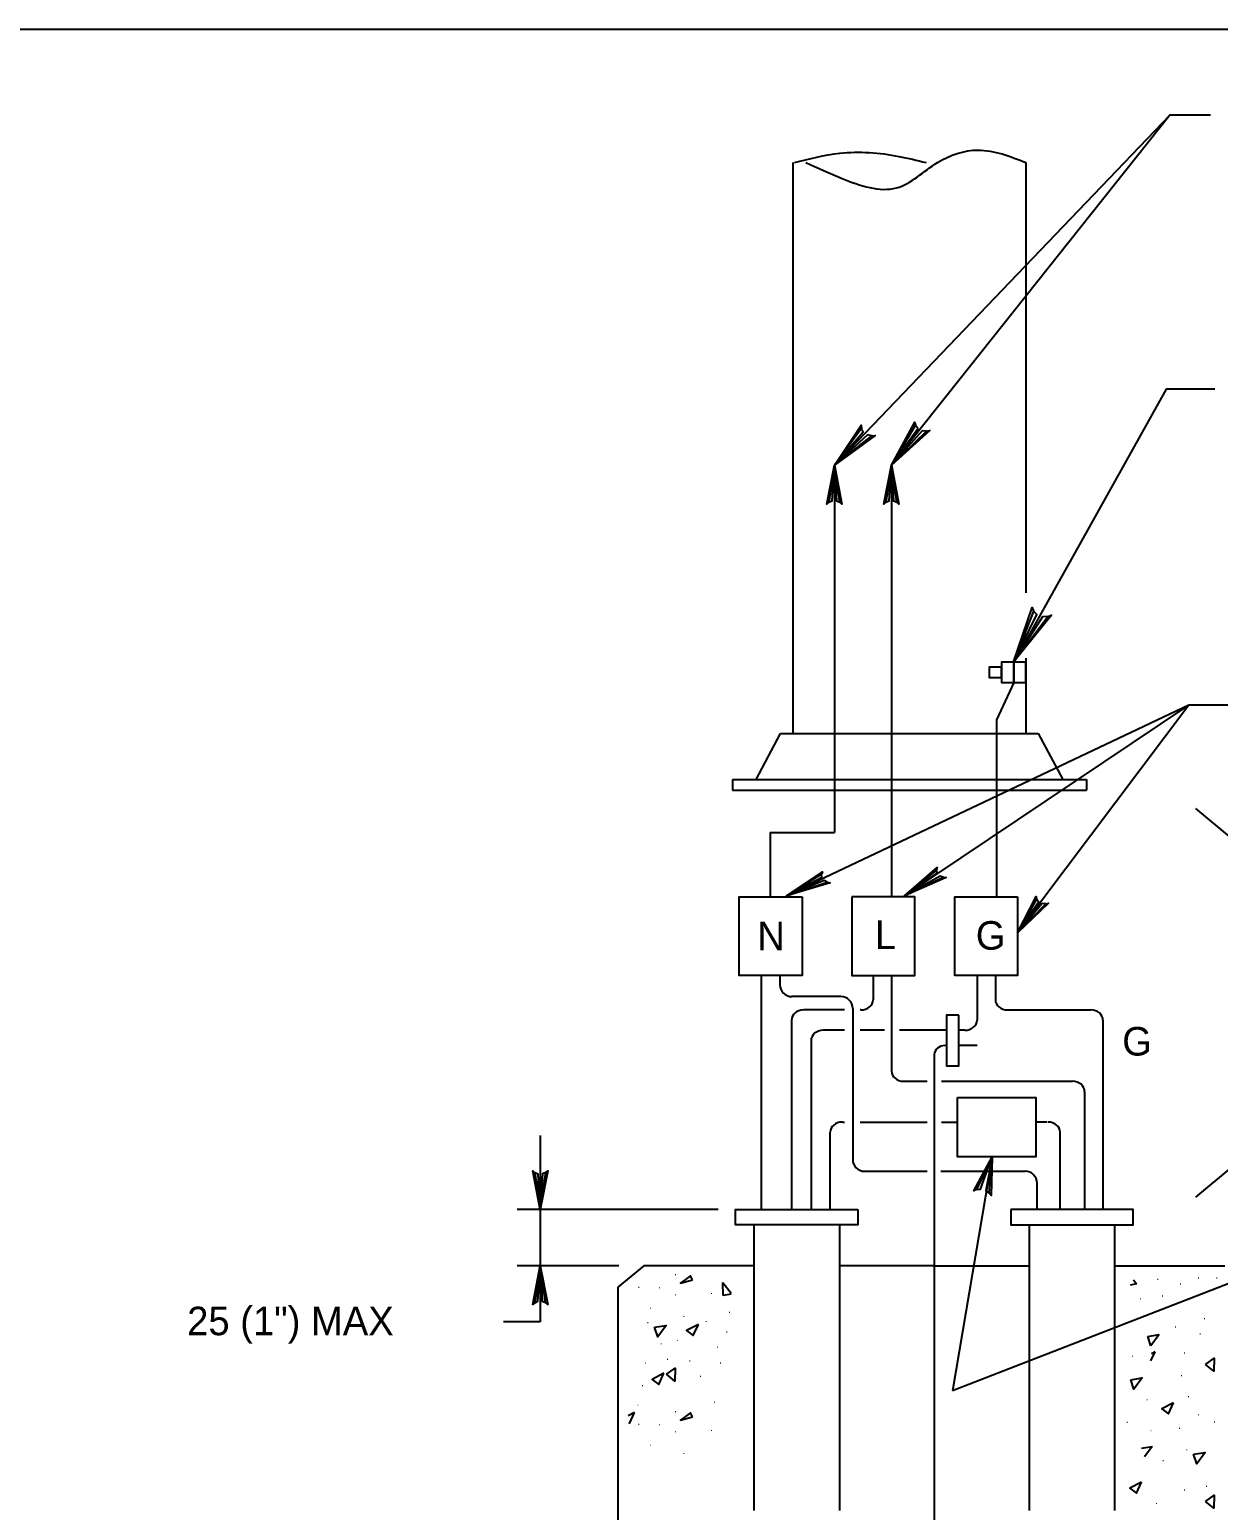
# Model space of a CAD drawing. Extents: x 638448 to 639352, y 297825 to 299013.
# Drawn here: x 639008.9 to 639148.9, y 298230 to 298404.3 of the extents above; entities that cross this region are included whole.
import ezdxf

# ---------------------------------------------------------------- set-up
doc = ezdxf.new("R2010")
doc.units = 0
for name, color, linetype in [('1', 7, 'Continuous'), ('2', 7, 'Continuous'), ('3', 7, 'Continuous')]:
    doc.layers.add(name, color=color, linetype=linetype)

msp = doc.modelspace()

# ---------------------------------------------------------------- linework, layer by layer
at = {"layer": '1'}
for p, q in [((639145.42, 298324.79), (639098.03, 298302.32)), ((639091.67, 298316.03), (639091.67, 298314.77)), ((639133.34, 298316.03), (639133.34, 298314.77)), ((639122.26, 298271.59), (639117.57, 298244.07)), ((639157.76, 298259.65), (639117.57, 298244.07))]:
    msp.add_line(p, q, dxfattribs=at)
msp.add_lwpolyline([(639272.65, 297840.29), (639272.65, 298404.29), (638486.65, 298404.29), (638486.65, 297840.29), (639272.65, 297840.29), (639272.65, 297866.65), (639072.65, 297866.65), (639072.65, 297931.33), (639272.65, 297931.33), (639272.65, 297960.29), (639072.65, 297960.29), (639072.65, 297840.29), (639151.45, 297840.29), (639151.45, 297866.65), (639151.45, 297840.29), (639228.45, 297840.29), (639228.45, 297866.65), (639228.45, 297854.33), (639272.65, 297854.33)], dxfattribs=at)
for centre, start, end in [((639098.66, 298291.87), 180, 270), ((639104.43, 298289.07), 0, 90), ((639107.23, 298271.31), 180, 270), ((639126.13, 298268.51), 0, 90)]:
    msp.add_arc(centre, 1.4, start, end, dxfattribs=at)
at = {"layer": '2'}
for p, q in [((639098.78, 298388.63), (639098.78, 298321.43)), ((639126.23, 298388.63), (639126.23, 298337.99)), ((639103.69, 298353.01), (639103.69, 298309.78)), ((639110.39, 298353.01), (639110.39, 298302.21)), ((639126.23, 298330.3), (639126.23, 298321.43)), ((639124.79, 298327.43), (639122.75, 298323.03)), ((639122.75, 298323.03), (639122.75, 298302.21)), ((639094.46, 298316.03), (639097.34, 298321.43)), ((639097.34, 298321.43), (639127.67, 298321.43)), ((639127.67, 298321.43), (639130.55, 298316.03)), ((639091.67, 298316.03), (639133.34, 298316.03)), ((639091.67, 298314.77), (639133.34, 298314.77)), ((639096.11, 298309.78), (639103.69, 298309.78)), ((639096.11, 298309.78), (639096.11, 298302.21)), ((639095.04, 298292.99), (639095.04, 298265.39)), ((639097.26, 298292.85), (639097.26, 298291.87)), ((639108.23, 298292.99), (639108.23, 298290.1)), ((639110.39, 298292.99), (639110.39, 298281.7)), ((639120.47, 298292.99), (639120.47, 298287.7)), ((639122.63, 298292.99), (639122.63, 298290.1)), ((639104.43, 298290.47), (639098.66, 298290.47)), ((639098.62, 298287.7), (639098.62, 298265.39)), ((639104.85, 298288.9), (639100.06, 298288.9)), ((639105.83, 298289.07), (639105.83, 298271.31)), ((639106.79, 298288.9), (639106.71, 298288.9)), ((639124.07, 298288.9), (639133.85, 298288.9)), ((639135.29, 298287.7), (639135.29, 298265.39)), ((639104.85, 298286.5), (639102.37, 298286.5)), ((639109.56, 298286.5), (639106.71, 298286.5)), ((639116.87, 298286.5), (639111.34, 298286.5)), ((639119.03, 298286.5), (639118.31, 298286.5)), ((639100.93, 298285.3), (639100.93, 298265.39)), ((639116.87, 298284.7), (639116.72, 298284.7)), ((639120.47, 298284.7), (639118.31, 298284.7)), ((639115.43, 298283.62), (639115.43, 298193.63)), ((639111.83, 298280.5), (639114.61, 298280.5)), ((639116.29, 298280.5), (639131.69, 298280.5)), ((639133.13, 298279.3), (639133.13, 298265.39)), ((639104.61, 298275.7), (639104.85, 298275.7)), ((639106.71, 298275.7), (639114.61, 298275.7)), ((639116.29, 298275.7), (639118.17, 298275.7)), ((639128.67, 298275.7), (639127.4, 298275.7)), ((639069.04, 298274.1), (639069.04, 298265.39)), ((639103.17, 298265.39), (639103.17, 298274.5)), ((639130.25, 298265.39), (639130.25, 298274.5)), ((639107.23, 298269.91), (639114.58, 298269.91)), ((639116.22, 298269.91), (639126.13, 298269.91)), ((639127.53, 298265.39), (639127.53, 298268.51)), ((639090.01, 298265.39), (639066.33, 298265.39)), ((639069.04, 298265.39), (639069.04, 298258.79)), ((639094.19, 298263.59), (639094.19, 298229.99)), ((639104.27, 298263.59), (639104.27, 298229.99)), ((639126.59, 298263.59), (639126.59, 298229.99)), ((639136.67, 298263.59), (639136.67, 298229.99)), ((639078.3, 298258.79), (639066.33, 298258.79)), ((639081.23, 298258.79), (639078.17, 298256.25)), ((639094.19, 298258.79), (639081.23, 298258.79)), ((639115.43, 298258.79), (639104.27, 298258.79)), ((639115.43, 298258.79), (639126.59, 298258.79)), ((639136.67, 298258.79), (639136.67, 298258.79)), ((639136.67, 298258.79), (639149.63, 298258.79)), ((639078.17, 298256.25), (639078.17, 298221.59)), ((639069.04, 298252.17), (639064.71, 298252.17))]:
    msp.add_line(p, q, dxfattribs=at)
for points in [[(639143.17, 298394.21), (639103.69, 298353.01)], [(639143.17, 298394.21), (639110.39, 298353.01)], [(639147.97, 298394.21), (639143.17, 298394.21)], [(639148.48, 298361.98), (639142.72, 298361.98), (639124.79, 298329.83)], [(639108.08, 298356.47), (639107.58, 298356.58), (639103.69, 298353.01), (639108.08, 298356.47), (639108.49, 298356.51), (639103.69, 298353.01), (639107.08, 298356.94), (639106.86, 298357.34), (639103.69, 298353.01), (639106.83, 298357.72), (639106.86, 298357.34)], [(639114.51, 298357.01), (639114.01, 298357.06), (639110.39, 298353.01), (639114.51, 298357.01), (639114.92, 298357.11), (639110.39, 298353.01), (639113.48, 298357.35), (639113.22, 298357.71), (639110.39, 298353.01), (639113.16, 298358.08), (639113.22, 298357.71)], [(639103.03, 298348.66), (639103.41, 298348.82), (639103.69, 298353.01), (639103.03, 298348.66), (639102.8, 298348.43), (639103.69, 298353.01), (639103.94, 298348.82), (639104.31, 298348.67), (639103.69, 298353.01), (639104.56, 298348.43), (639104.31, 298348.67)], [(639109.73, 298348.66), (639110.11, 298348.82), (639110.39, 298353.01), (639109.73, 298348.66), (639109.5, 298348.43), (639110.39, 298353.01), (639110.64, 298348.82), (639111.01, 298348.67), (639110.39, 298353.01), (639111.26, 298348.43), (639111.01, 298348.67)], [(639128.79, 298335.2), (639128.18, 298335.18), (639124.76, 298329.84), (639128.79, 298335.2), (639129.25, 298335.38), (639124.76, 298329.84), (639127.49, 298335.44), (639127.11, 298335.83), (639124.76, 298329.84), (639126.95, 298336.27), (639127.11, 298335.83)], [(639111.92, 298302.32), (639145.42, 298324.79)], [(639157.46, 298324.79), (639145.42, 298324.79), (639125.23, 298297.98)], [(639146.23, 298266.84), (639154.38, 298273.63), (639154.38, 298288.03), (639156.42, 298289.73), (639154.38, 298291.42), (639154.38, 298305.82), (639146.23, 298312.61)], [(639102.84, 298303.93), (639102.47, 298304.13), (639098.03, 298302.32), (639102.84, 298303.93), (639103.19, 298303.87), (639098.03, 298302.32), (639102.2, 298304.52), (639102.16, 298304.87), (639098.03, 298302.32), (639102.28, 298305.16), (639102.16, 298304.87)], [(639116.49, 298304.51), (639116.11, 298304.66), (639111.92, 298302.32), (639116.49, 298304.51), (639116.85, 298304.49), (639111.92, 298302.32), (639115.79, 298305.01), (639115.71, 298305.35), (639111.92, 298302.32), (639115.79, 298305.66), (639115.71, 298305.35)], [(639128.57, 298301.38), (639128.14, 298301.41), (639125.23, 298297.98), (639128.57, 298301.38), (639128.9, 298301.47), (639125.23, 298297.98), (639127.69, 298301.64), (639127.48, 298301.94), (639125.23, 298297.98), (639127.41, 298302.25), (639127.48, 298301.94)], [(639120.41, 298267.76), (639120.89, 298267.79), (639122.26, 298271.59), (639120.41, 298267.76), (639120.09, 298267.62), (639122.26, 298271.59), (639121.5, 298267.62), (639121.9, 298267.37), (639122.26, 298271.59), (639122.13, 298267.07), (639121.9, 298267.37)], [(639069.7, 298269.75), (639069.32, 298269.59), (639069.04, 298265.39), (639069.7, 298269.75), (639069.93, 298269.97), (639069.04, 298265.39), (639068.8, 298269.58), (639068.42, 298269.74), (639069.04, 298265.39), (639068.17, 298269.97), (639068.42, 298269.74)], [(639068.39, 298254.43), (639068.77, 298254.6), (639069.04, 298258.79), (639068.39, 298254.43), (639068.16, 298254.21), (639069.04, 298258.79), (639069.29, 298254.6), (639069.67, 298254.45), (639069.04, 298258.79), (639069.92, 298254.21), (639069.67, 298254.45)], [(639069.04, 298258.79), (639069.04, 298252.17)], [(639090.59, 298255.28), (639090.55, 298256.81)], [(639090.55, 298256.81), (639091.52, 298255.56)], [(639139.23, 298256.64), (639138.51, 298256.5)], [(639138.87, 298257.11), (639139.23, 298256.64)], [(639091.51, 298255.45), (639090.59, 298255.28)], [(639140.56, 298250.47), (639141.91, 298250.69)], [(639140.94, 298249.36), (639140.56, 298250.47)], [(639141.91, 298250.69), (639140.94, 298249.36)], [(639140.94, 298247.59), (639141.42, 298248.65)], [(639141.42, 298248.65), (639140.99, 298248.43)], [(639080.16, 298241.5), (639079.41, 298241.11)], [(639079.56, 298240.2), (639080.16, 298241.5)], [(639079.46, 298240.28), (639079.56, 298240.2)], [(639139.81, 298237.31), (639141.09, 298237.52)], [(639141.09, 298237.52), (639140.2, 298236.29)]]:
    msp.add_lwpolyline(points, dxfattribs=at)
for points in [[(639124.79, 298327.43), (639124.79, 298329.83), (639123.35, 298329.83), (639123.35, 298327.43)], [(639126.23, 298327.43), (639126.23, 298329.83), (639124.79, 298329.83), (639124.79, 298327.43)], [(639123.35, 298328.03), (639123.35, 298329.23), (639121.91, 298329.23), (639121.91, 298328.03)], [(639099.87, 298302.21), (639099.87, 298292.97), (639092.48, 298292.97), (639092.48, 298302.21)], [(639105.74, 298302.21), (639105.74, 298292.97), (639113.13, 298292.97), (639113.13, 298302.21)], [(639125.23, 298302.21), (639125.23, 298292.97), (639117.84, 298292.97), (639117.84, 298302.21)], [(639118.31, 298288.3), (639116.87, 298288.3), (639116.87, 298282.3), (639118.31, 298282.3)], [(639118.17, 298278.6), (639127.4, 298278.6), (639127.4, 298271.59), (639118.17, 298271.59)], [(639106.43, 298265.39), (639106.43, 298263.59), (639092.03, 298263.59), (639092.03, 298265.39)], [(639124.43, 298265.39), (639124.43, 298263.59), (639138.83, 298263.59), (639138.83, 298265.39)], [(639086.98, 298257.14), (639086.74, 298257.6), (639085.56, 298256.75)], [(639082.51, 298251.54), (639083.86, 298251.77), (639082.89, 298250.43)], [(639087.66, 298251.88), (639086.28, 298251.16), (639087.06, 298250.58)], [(639147.35, 298247.17), (639148.39, 298247.92), (639148.34, 298246.37)], [(639083.61, 298246.13), (639082.23, 298245.41), (639083.01, 298244.82)], [(639083.91, 298246.01), (639084.94, 298246.75), (639084.9, 298245.2)], [(639138.56, 298245.37), (639139.91, 298245.59), (639138.94, 298244.26)], [(639143.61, 298242.67), (639142.23, 298241.95), (639143.01, 298241.37)], [(639086.98, 298241.01), (639086.74, 298241.47), (639085.56, 298240.62)], [(639145.96, 298236.59), (639147.31, 298236.81), (639146.34, 298235.47)], [(639139.84, 298233.33), (639138.46, 298232.61), (639139.24, 298232.03)], [(639147.35, 298231.05), (639148.39, 298231.8), (639148.34, 298230.24)]]:
    msp.add_lwpolyline(points, close=True, dxfattribs=at)
for centre, major_axis, start_param, end_param in [((639106.79, 298290.1), (1.44, 0), 4.712389, 6.283185), ((639124.07, 298290.1), (-1.44, 0), 0, 1.570796), ((639100.06, 298287.7), (-1.44, 0), 4.712389, 6.283185), ((639119.03, 298287.7), (1.44, 0), 4.712389, 6.283185), ((639133.85, 298287.7), (1.44, 0), 0, 1.570796), ((639102.37, 298285.3), (-1.44, 0), 4.712389, 6.283185), ((639116.72, 298283.62), (-1.3, 0), 4.712389, 6.283185), ((639111.83, 298281.7), (-1.44, 0), 0, 1.570796), ((639131.69, 298279.3), (1.44, 0), 0, 1.570796), ((639104.61, 298274.5), (-1.44, 0), 4.712389, 6.283185), ((639128.81, 298274.5), (1.44, 0), 0, 1.570796)]:
    msp.add_ellipse(centre, major_axis=major_axis, ratio=0.833333, start_param=start_param, end_param=end_param, dxfattribs=at)
for points in [[(639098.96, 298388.63), (639104.31, 298389.74), (639111.25, 298389.37), (639114.46, 298388.63)], [(639100.31, 298388.63), (639104.58, 298386.77), (639110.99, 298385.66), (639115.8, 298388.63), (639120.61, 298390.11), (639126.23, 298388.63)]]:
    msp.add_spline(points, degree=3, dxfattribs=at)

# ---------------------------------------------------------------- texts
for p in [(639080.47, 298256.17), (639082.92, 298256.11), (639084.81, 298257.67), (639141.6, 298257.12), (639144.26, 298256.56), (639146.36, 298257.28), (639148.54, 298257.28), (639084.81, 298255.29), (639089.03, 298255.45), (639139.53, 298254.82), (639142.12, 298255.16), (639081.84, 298253.71), (639085.8, 298252.74), (639091.16, 298253.24), (639081.54, 298252.01), (639081.54, 298252.01), (639088.4, 298252.16), (639090.84, 298250.91), (639143.66, 298251.51), (639147.09, 298252.49), (639083.11, 298249.52), (639085.06, 298249.91), (639089.75, 298249.14), (639146.56, 298250.69), (639083.86, 298247.71), (639086.48, 298247.5), (639138.6, 298248.07), (639144.74, 298248.45), (639081.29, 298247.28), (639087.74, 298245.7), (639090.09, 298247.28), (639144.37, 298245.78), (639080.92, 298244.61), (639080.39, 298242.31), (639089.38, 298242.66), (639140.32, 298242.93), (639145.2, 298243.3), (639084.81, 298241.54), (639146.36, 298241.16), (639148.25, 298240.33), (639080.47, 298240.04), (639082.92, 298239.99), (639084.81, 298239.16), (639089.03, 298239.32), (639137.99, 298240.29), (639140.78, 298239.29), (639144.13, 298239.57), (639081.84, 298237.59), (639144.99, 298237.05), (639144.99, 298237.05), (639085.8, 298236.62), (639142.2, 298235.77), (639144.74, 298232.32), (639147.31, 298232.76), (639141.42, 298230.74)]:
    msp.add_text('.', height=0.893, dxfattribs=at).set_placement(p)
at = {"layer": '3'}
for s, p in [('N', (639094.6, 298295.92)), ('G', (639120.32, 298295.99)), ('G', (639137.56, 298283.53)), ('25 (1") MAX', (639027.48, 298250.61))]:
    msp.add_text(s, height=3.36, dxfattribs=at).set_placement(p)
msp.add_text('L', height=3.36, rotation=360, dxfattribs=at).set_placement((639108.44, 298296.07))

doc.saveas('drawing.dxf')
